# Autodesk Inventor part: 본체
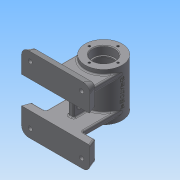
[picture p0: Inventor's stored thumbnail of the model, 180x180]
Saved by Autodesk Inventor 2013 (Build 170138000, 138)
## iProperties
Created: 2016-07
Part Number: 본체
Material: 일반
Document SubType Name: Modeling
Designer: Administrator
Density: 1 g/cm^3
Author: Administrator
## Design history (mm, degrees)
sketch "스케치1"
  geometry: L1 (40, -55)-(-40, -55); L2 (-50, -45)-(-50, 45); L3 (-40, 55)-(40, 55); L4 (50, 45)-(50, -45); L5 (50, -55)-(-50, 55); L6 (-50, -55)-(50, 55); A1 r 10 centre (-40, 45) between (-40, 55) and (-50, 45); A2 r 10 centre (40, 45) between (50, 45) and (40, 55); A3 r 10 centre (40, -45) between (40, -55) and (50, -45); A4 r 10 centre (-40, -45) between (-50, -45) and (-40, -55); 1 further point
  constraints: 12 end point, 8 point on circle, 8 point on line, 8 tangent, 4 centre point, 3 equal radius, 2 midpoint, 2 parallel, 1 horizontal, 1 perpendicular
  dimensions: "d0" = 100 distance of L5.end L6.end; "d1" = 110 distance of L6.start L5.end; "d8" = 10 radius of A1
node "작업 평면1"
sketch "스케치2"
  geometry: L1 (-40.632, 50.632)-(40.632, 50.632); L2 (45.632, 45.632)-(45.632, -45.632); L3 (40.632, -50.632)-(-40.632, -50.632); L4 (-45.632, -45.632)-(-45.632, 45.632); A1 r 5 centre (-40.632, 45.632) between (-40.632, 50.632) and (-45.632, 45.632); A2 r 5 centre (-40.632, -45.632) between (-45.632, -45.632) and (-40.632, -50.632); A3 r 5 centre (40.632, -45.632) between (40.632, -50.632) and (45.632, -45.632); A4 r 5 centre (40.632, 45.632) between (45.632, 45.632) and (40.632, 50.632); 4 further points
  constraints: 8 end point, 8 point on circle, 8 tangent, 6 point on line, 4 centre point, 3 equal radius, 2 parallel, 1 horizontal, 1 perpendicular
  dimensions: "d9" = 5 radius of A1
feature "로프트1" sketch "스케치2" dims "d4" = 0, "d5" = 90 deg, "d6" = 0, "d7" = 90 deg
sketch "스케치3"
  geometry: L1 (-9.368, 5.632)-(-9.368, 95.632) reference; L2 (90.632, 95.632)-(90.632, 5.632) reference; L3 (90.632, 30.632)-(-9.368, 30.632); L4 (-9.368, 30.632)-(-9.368, 70.632); L5 (-9.368, 70.632)-(90.632, 70.632); L6 (90.632, 70.632)-(90.632, 30.632); L7 (90.632, 30.632)-(-9.368, 70.632); L8 (-9.368, 30.632)-(90.632, 70.632); L9 (0.632, 105.632)-(80.632, 105.632) reference; 1 further point
  constraints: 12 end point, 2 midpoint, 2 parallel, 1 horizontal, 1 perpendicular, 1 point on line
  dimensions: "d10" = 35 distance between parallel lines of L9 L5
extrude "돌출2" cut sketch "스케치3" distance "d11" = 12; taper "d12" = 0 deg
sketch "스케치4"
  geometry: L1 (40, 0)-(-40, 0) reference; C1 r 27 at (0, 70); 2 further points
  constraints: 1 centre point, 1 midpoint, 1 vertical alignment
  dimensions: "d13" = 54 diameter of C1; "d15" = 70 distance from line of L1 C1.centre
extrude "돌출3" join sketch "스케치4" stored distance "d16" = 70; taper "d17" = 0 deg
hole "구멍1" diameter "d20" = 28; stored, may be unused: countersink angle "d24" = 90 deg, drill point angle "d26" = 0 deg; dims "d18" = 10, "d19" = 10, "d21" = 6, "d22" = 32, "d23" = 12, "d25" = 2
sketch "스케치5"
  geometry: C1 r 14 at (0, 0) reference; C2 r 22 at (0, 0); 1 further point
  constraints: 1 centre point, 1 coincident
  dimensions: "d27" = 44 diameter of C2
extrude "돌출4" cut sketch "스케치5" distance "d28" = 42; taper "d29" = 0 deg
hole "구멍2" diameter "d32" = 28; stored, may be unused: countersink angle "d36" = 90 deg, drill point angle "d38" = 0 deg; dims "d30" = 10, "d31" = 10, "d33" = 6, "d34" = 32, "d35" = 12, "d37" = 2
chamfer "모따기1" distance "d39" = 1; stored, may be unused: second distance "d40" = 2, angle "d41" = 45 deg
chamfer "모따기2" distance "d42" = 1; stored, may be unused: second distance "d43" = 2, angle "d44" = 45 deg
fillet "모깎기1" dims "d45" = 0.3
fillet "모깎기2" dims "d46" = 2
sketch "스케치6"
  geometry: L1 (-5, 5)-(-5, 30.632) reference; L2 (-5, 30.632)-(86.265, 30.632) reference; L3 (86.265, 30.632)-(86.265, 5) reference; L4 (81.265, 0)-(0, 0) reference; L5 (86.265, 70.632)-(-5, 70.632) reference; L6 (-5, 70.632)-(-5, 96.265) reference; L7 (0, 101.265)-(81.265, 101.265) reference; L8 (86.265, 96.265)-(86.265, 70.632) reference; L9 (67.632, 22.632)-(13.632, 22.632); L10 (13.632, 22.632)-(13.632, 78.632); L11 (13.632, 78.632)-(67.632, 78.632); L12 (67.632, 78.632)-(67.632, 22.632); L13 (67.632, 22.632)-(13.632, 78.632); L14 (13.632, 22.632)-(67.632, 78.632); A1 r 5 centre (0, 5) between (-5, 5) and (0, 0) reference; A2 r 5 centre (81.265, 5) between (81.265, 0) and (86.265, 5) reference; A3 r 5 centre (0, 96.265) between (0, 101.265) and (-5, 96.265) reference; A4 r 5 centre (81.265, 96.265) between (86.265, 96.265) and (81.265, 101.265) reference; 5 further points
  constraints: 12 end point, 8 point on line, 2 midpoint, 2 parallel, 1 horizontal, 1 perpendicular
  dimensions: "d47" = 8 distance between parallel lines of L5 L11; "d48" = 54 distance of L10.end L11.end
extrude "돌출5" join sketch "스케치6" stored distance "d49" = 42; taper "d50" = 0 deg
sketch "스케치7"
  geometry: L1 (86, 23.3)-(86, 34) reference; L2 (86, 34)-(87, 35) reference; L3 (87, 35)-(97, 35) reference; L4 (97, 35)-(97, -35) reference; L5 (97, -35)-(87, -35) reference; L6 (87, -35)-(86, -34) reference; L7 (86, -34)-(86, -23.3) reference; L8 (85.7, -23)-(84, -23) reference; L9 (84, -23)-(84, -21) reference; L10 (84, -21)-(90, -21) reference; L11 (92, -19)-(92, 19) reference; L12 (90, 21)-(84, 21) reference; L13 (84, 21)-(84, 23) reference; L14 (84, 23)-(85.7, 23) reference; L15 (54.3, 23)-(56, 23) reference; L16 (56, 23)-(56, 21) reference; L17 (56, 21)-(50, 21) reference; L18 (48, 19)-(48, -19) reference; L19 (50, -21)-(56, -21) reference; L20 (56, -21)-(56, -23) reference; L21 (56, -23)-(54.3, -23) reference; L22 (54, -23.3)-(54, -34) reference; L23 (54, -34)-(53, -35) reference; L24 (53, -35)-(43, -35) reference; L25 (43, -35)-(43, -28) reference; L26 (43, -28)-(12, -28) reference; L27 (12, -28)-(12, -50.632) reference; L28 (12, -50.632)-(0, -55) reference; L29 (0, -55)-(0, -20) reference; L30 (0, -20)-(43, -20) reference; L31 (43, -20)-(43, 20) reference; L32 (43, 20)-(0, 20) reference; L33 (0, 20)-(0, 55) reference; L34 (0, 55)-(12, 50.632) reference; L35 (12, 50.632)-(12, 28) reference; L36 (12, 28)-(43, 28) reference; L37 (43, 28)-(43, 35) reference; L38 (43, 35)-(53, 35) reference; L39 (53, 35)-(54, 34) reference; L40 (54, 34)-(54, 23.3) reference; L41 (45.5, 20)-(22, 20); L42 (22, 20)-(22, -20); L43 (22, -20)-(45.5, -20); L44 (45.5, -20)-(45.5, 20); A1 r 0.3 centre (85.7, 23.3) between (85.7, 23) and (86, 23.3) reference; A2 r 0.3 centre (85.7, -23.3) between (86, -23.3) and (85.7, -23) reference; A3 r 2 centre (90, -19) between (90, -21) and (92, -19) reference; A4 r 2 centre (90, 19) between (92, 19) and (90, 21) reference; A5 r 0.3 centre (54.3, 23.3) between (54, 23.3) and (54.3, 23) reference; A6 r 2 centre (50, 19) between (50, 21) and (48, 19) reference; A7 r 2 centre (50, -19) between (48, -19) and (50, -21) reference; A8 r 0.3 centre (54.3, -23.3) between (54.3, -23) and (54, -23.3) reference; 1 further point
  constraints: 8 end point, 2 parallel, 1 horizontal, 1 perpendicular, 1 point on line
  dimensions: "d51" = 21 distance between parallel lines of L42 L31
extrude "돌출6" join sketch "스케치7" stored distance "d52" = 8; taper "d53" = 0 deg
sketch "스케치8"
  geometry: L1 (-8, 35.5)-(8, 35.5); L2 (8, 28.5)-(-8, 28.5); L3 (45, 0)-(20, 0) reference; A1 r 3.5 centre (-8, 32) between (-8, 35.5) and (-8, 28.5); A2 r 3.5 centre (8, 32) between (8, 28.5) and (8, 35.5); 3 further points
  constraints: 4 end point, 4 point on circle, 3 tangent, 2 centre point, 2 midpoint, 2 vertical alignment, 1 horizontal alignment
  dimensions: "d54" = 7 diameter of A1; "d55" = 7 diameter of A2; "d56" = 23 dimension on A2 A1; "d57" = 32 distance from line of L3 A1.centre
extrude "돌출7" cut sketch "스케치8" stored distance "d58" = 8; taper "d59" = 0 deg
fillet "모깎기3" dims "d60" = 2
fillet "모깎기4" dims "d61" = 2
fillet "모깎기5" dims "d62" = 2
sketch "스케치9"
  geometry: L1 (78.063, 6.732)-(3.063, 6.732); L2 (3.063, 6.732)-(3.063, 91.732); L3 (3.063, 91.732)-(78.063, 91.732); L4 (78.063, 91.732)-(78.063, 6.732); L5 (78.063, 6.732)-(3.063, 91.732); L6 (3.063, 6.732)-(78.063, 91.732); 5 further points
  constraints: 12 end point, 4 coincident, 2 midpoint, 2 parallel, 1 horizontal, 1 perpendicular
  dimensions: "d63" = 75 distance of L2.end L3.end; "d64" = 85 distance of L1.end L2.end
hole "구멍3" sketch "스케치9" at (3.063, 91.732), (3.063, 6.732), (78.063, 6.732), (78.063, 91.732) diameter "d65" = 6; stored, may be unused: countersink angle "d69" = 90 deg, drill point angle "d71" = 0 deg; dims "d66" = 6, "d67" = 10, "d68" = 4, "d70" = 2
sketch "스케치10" dims "d72" = 42
  geometry: C1 r 17 at (0, 0) reference; 3 further points
  constraints: 2 vertical alignment, 1 coincident, 2 other
hole "구멍4" sketch "스케치10" at (0, 21) diameter "d73" = 3.242; stored, may be unused: countersink angle "d77" = 90 deg, drill point angle "d79" = 118 deg; dims "d74" = 8, "d75" = 32, "d76" = 2, "d78" = 10
node "작업 평면2"
sketch "스케치11"
  geometry: L1 (-13, 90)-(-67, 90) reference; L2 (10, 100)-(10, 75) reference; C1 r 5 at (-40, 68); 1 further point
  constraints: 1 centre point
  dimensions: "d84" = 10 diameter of C1; "d85" = 22 distance from line of L1 C1.centre; "d86" = 50 distance from line of L2 C1.centre
extrude "돌출8" join sketch "스케치11" stored distance "d87" = 8; taper "d88" = 0 deg
hole "구멍5" diameter "d91" = 5.188; stored, may be unused: countersink angle "d95" = 90 deg, drill point angle "d97" = 118 deg; dims "d89" = 10, "d90" = 10, "d92" = 8, "d93" = 32, "d94" = 2, "d96" = 10
sketch "스케치12"
  geometry: L1 (4, 26.5)-(4, 22) reference; L2 (4, 22)-(-4, 22) reference; L3 (-4, 22)-(-4, 26.5) reference; L4 (-2, 28.5)-(2, 28.5) reference; L5 (-4, 37.5)-(-4, 43.298) reference; L6 (4, 43.298)-(4, 37.5) reference; L7 (2, 35.5)-(-2, 35.5) reference; L8 (0, 70)-(0, 28.5); L9 (0, 70)-(-15.898, 44.559); C1 r 22 at (0, 70) reference; A1 r 2 centre (-2, 26.5) between (-2, 28.5) and (-4, 26.5) reference; A2 r 2 centre (2, 26.5) between (4, 26.5) and (2, 28.5) reference; A3 r 27 centre (0, 70) between (4, 43.298) and (-4, 43.298) reference; A4 r 2 centre (2, 37.5) between (2, 35.5) and (4, 37.5) reference; A5 r 2 centre (-2, 37.5) between (-4, 37.5) and (-2, 35.5) reference; 1 further point
  constraints: 4 end point, 1 midpoint
  dimensions: "d99" = 30 distance of L8.start L9.end; "d100" = 32 deg angle of L9 L8
  node "절단 모서리 투영3"
node "작업 평면3"
sketch "스케치13"
  geometry: C1 r 6 at (0, 0); 1 further point
  constraints: 1 centre point
  dimensions: "d101" = 12 diameter of C1
extrude "돌출9" join sketch "스케치13" stored distance "d103" = 8; taper "d104" = 0 deg
sketch "스케치14"
  geometry: C1 r 6 at (0, 0) reference; 1 further point
hole "구멍6" sketch "스케치14" at (0, 0) diameter "d105" = 5.188; stored, may be unused: countersink angle "d109" = 90 deg, drill point angle "d111" = 118 deg; dims "d106" = 8, "d107" = 32, "d108" = 2, "d110" = 10
node "작업 평면4"
sketch "스케치15"
  geometry: L1 (-58, 49.232)-(-58, 29.464) reference; L2 (-56, 26)-(0, 26) reference; L3 (0, 26)-(0, 35) reference; L4 (-70, 55)-(-59.316, 51.111) reference; L5 (-70, 20)-(-70, 55) reference; L6 (-59.464, 20)-(-70, 20) reference; L7 (-56, 26)-(-56, 22) reference; L8 (0, 22)-(0, 26) reference; L9 (0, -22)-(0, 22) reference; L10 (0, -26)-(0, -22) reference; L11 (0, -35)-(0, -26) reference; L12 (-56, 22)-(0, 22) reference; L13 (-56, -22)-(0, -22) reference; L14 (-56, -22)-(-56, -26) reference; L15 (-56, -26)-(0, -26) reference; L16 (-70, -20)-(-59.464, -20) reference; L17 (-70, -55)-(-70, -20) reference; L18 (-59.316, -51.111)-(-70, -55) reference; L19 (-58, -29.464)-(-58, -49.232) reference; A1 r 2 centre (-60, 49.232) between (-58, 49.232) and (-59.316, 51.111) reference; A2 r 2 centre (-60, -49.232) between (-59.316, -51.111) and (-58, -49.232) reference; 3 further points
  constraints: 1 coincident, 1 midpoint, 5 other
feature "엠보싱1" sketch "스케치15" dims "d0" = 100, "d1" = 110, "d8" = 10, "d112" = 0.5, "d113" = 0
fillet "모깎기6" dims "d114" = 2
node "솔리드2"
mirror "대칭1"
pattern_circular "원형 패턴1" dims angle "d81" = 360 deg
mirror "대칭2"
node "절단 모서리 투영1"
node "절단 모서리 투영2"
node "절단 모서리 투영4"
